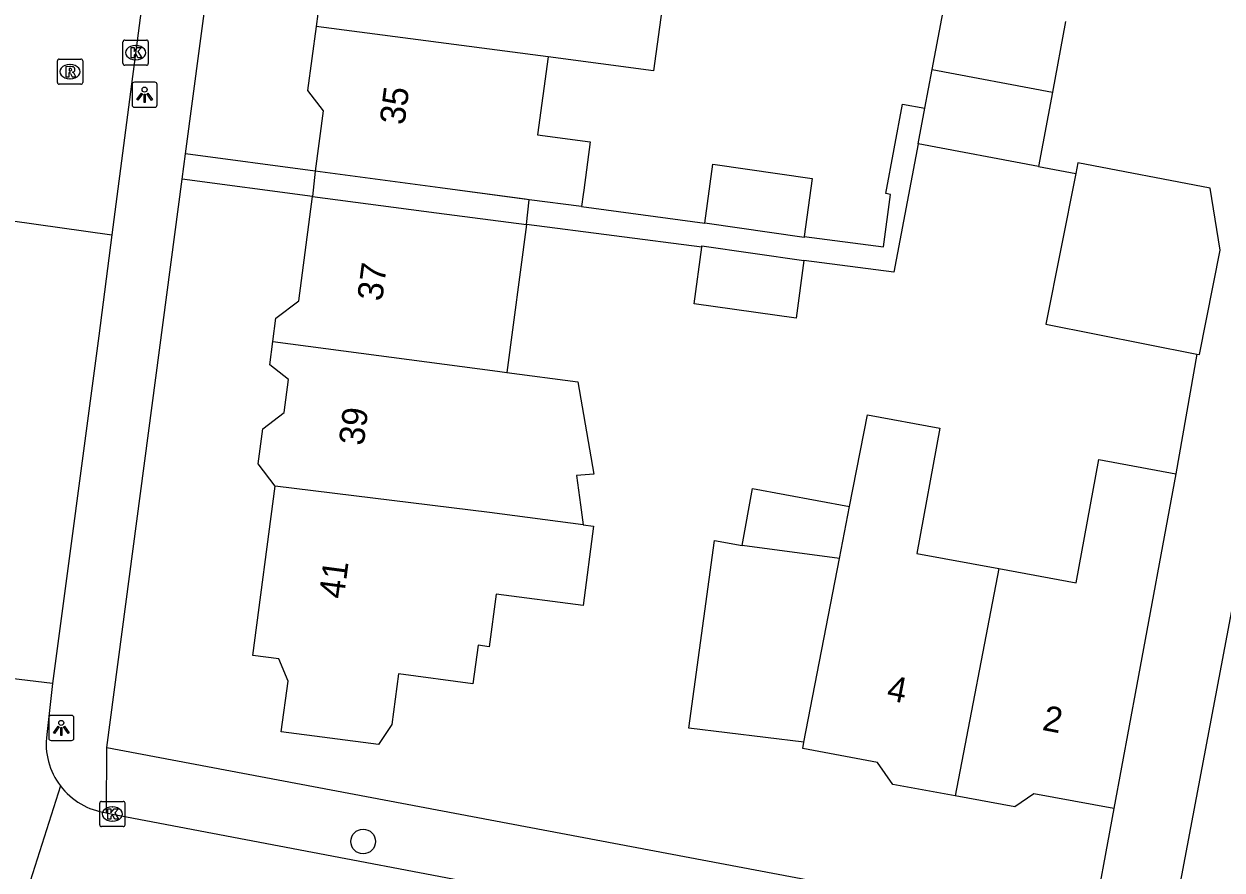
# Model space of a CAD drawing. Extents: x 161258 to 161838, y 380836 to 381727.
# Drawn here: x 161739.61 to 161787.11, y 381543.22 to 381576.79 of the extents above; entities that cross this region are included whole.
import ezdxf

# ---------------------------------------------------------------- set-up
doc = ezdxf.new("R2010")
doc.units = 0
for name, color, linetype in [('IMGEO_Boom', 7, 'Continuous'), ('IMGEO_Kolk', 7, 'Continuous'), ('IMGEO_Lichtpunt', 7, 'Continuous'), ('IMGEO_Pand', 7, 'Continuous'), ('IMGEO_Pand_nummerreeks', 7, 'Continuous'), ('IMGEO_Pand_overbouw', 7, 'Continuous'), ('IMGEO_Rijbaan_lokaal_open', 7, 'Continuous'), ('IMGEO_Rioolput', 7, 'Continuous'), ('IMGEO_Voetpad_open', 7, 'Continuous')]:
    doc.layers.add(name, color=color, linetype=linetype)

msp = doc.modelspace()

# ---------------------------------------------------------------- linework, layer by layer
at = {"layer": 'IMGEO_Boom'}
msp.add_circle((161753.055, 381544.356), 0.489, dxfattribs=at)
at = {"layer": 'IMGEO_Kolk'}
for p, q in [((161743.533, 381575.221), (161743.533, 381576.073)), ((161743.608, 381576.147), (161744.46, 381576.147)), ((161744.021, 381575.927), (161744.046, 381575.927)), ((161744.534, 381576.073), (161744.534, 381575.221)), ((161744.044, 381575.367), (161744.019, 381575.367)), ((161744.46, 381575.147), (161743.608, 381575.147)), ((161742.686, 381545.945), (161743.538, 381545.945)), ((161742.611, 381545.019), (161742.611, 381545.871)), ((161743.099, 381545.725), (161743.124, 381545.725)), ((161743.612, 381545.871), (161743.612, 381545.019)), ((161743.538, 381544.945), (161742.686, 381544.945)), ((161743.122, 381545.165), (161743.097, 381545.165))]:
    msp.add_line(p, q, dxfattribs=at)
for points in [[(161743.533, 381575.221), (161743.533, 381576.073)], [(161743.608, 381576.147), (161744.46, 381576.147)], [(161743.854, 381575.847), (161743.977, 381575.847), (161743.977, 381575.696), (161744.107, 381575.847), (161744.271, 381575.847), (161744.125, 381575.696), (161744.278, 381575.447), (161744.126, 381575.447), (161744.041, 381575.611), (161743.977, 381575.544), (161743.977, 381575.447), (161743.854, 381575.447), (161743.854, 381575.847)], [(161744.534, 381576.073), (161744.534, 381575.221)], [(161744.46, 381575.147), (161743.608, 381575.147)], [(161742.686, 381545.945), (161743.538, 381545.945)], [(161742.611, 381545.019), (161742.611, 381545.871)], [(161742.932, 381545.645), (161743.055, 381545.645), (161743.055, 381545.494), (161743.185, 381545.645), (161743.349, 381545.645), (161743.203, 381545.494), (161743.356, 381545.245), (161743.204, 381545.245), (161743.119, 381545.409), (161743.055, 381545.342), (161743.055, 381545.245), (161742.932, 381545.245), (161742.932, 381545.645)], [(161743.612, 381545.871), (161743.612, 381545.019)], [(161743.538, 381544.945), (161742.686, 381544.945)]]:
    msp.add_lwpolyline(points, dxfattribs=at)
for centre, start, end in [((161743.61, 381576.071), 91.552, 178.448), ((161743.61, 381576.071), 91.552, 178.448), ((161744.458, 381576.071), 1.552, 88.448), ((161744.458, 381576.071), 1.552, 88.448), ((161743.61, 381575.223), 181.552, 268.448), ((161743.61, 381575.223), 181.552, 268.448), ((161744.458, 381575.223), 271.552, 358.448), ((161744.458, 381575.223), 271.552, 358.448), ((161742.688, 381545.869), 91.552, 178.448), ((161742.688, 381545.869), 91.552, 178.448), ((161743.536, 381545.869), 1.552, 88.448), ((161743.536, 381545.869), 1.552, 88.448), ((161742.688, 381545.021), 181.552, 268.448), ((161742.688, 381545.021), 181.552, 268.448), ((161743.536, 381545.021), 271.552, 358.448), ((161743.536, 381545.021), 271.552, 358.448)]:
    msp.add_arc(centre, 0.0765, start, end, dxfattribs=at)
for centre, major_axis, ratio, start_param, end_param in [((161744.02, 381575.647), (-0.387, 0.002), 0.722429, 4.712389, 7.853982), ((161744.045, 381575.647), (-0.39, 0.002), 0.717154, 1.570796, 4.712389), ((161743.098, 381545.445), (-0.387, 0.002), 0.722429, 4.712389, 7.853982), ((161743.123, 381545.445), (-0.39, 0.002), 0.717154, 1.570796, 4.712389)]:
    msp.add_ellipse(centre, major_axis=major_axis, ratio=ratio, start_param=start_param, end_param=end_param, dxfattribs=at)
at = {"layer": 'IMGEO_Lichtpunt'}
for p, q in [((161744.793, 381574.478), (161743.985, 381574.478)), ((161744.793, 381574.478), (161743.985, 381574.478)), ((161743.891, 381574.383), (161743.891, 381573.576)), ((161743.891, 381574.383), (161743.891, 381573.576)), ((161744.887, 381573.576), (161744.887, 381574.383)), ((161744.887, 381573.576), (161744.887, 381574.383)), ((161743.985, 381573.482), (161744.793, 381573.482)), ((161743.985, 381573.482), (161744.793, 381573.482)), ((161740.588, 381549.263), (161740.588, 381548.456)), ((161740.588, 381549.263), (161740.588, 381548.456)), ((161741.49, 381549.358), (161740.682, 381549.358)), ((161741.49, 381549.358), (161740.682, 381549.358)), ((161741.584, 381548.456), (161741.584, 381549.263)), ((161741.584, 381548.456), (161741.584, 381549.263)), ((161740.682, 381548.362), (161741.49, 381548.362)), ((161740.682, 381548.362), (161741.49, 381548.362))]:
    msp.add_line(p, q, dxfattribs=at)
for points in [[(161744.265, 381574.047), (161744.304, 381574.019), (161744.116, 381573.757), (161744.078, 381573.784), (161744.265, 381574.047)], [(161744.367, 381573.999), (161744.414, 381573.999), (161744.414, 381573.677), (161744.367, 381573.677), (161744.367, 381573.999)], [(161744.477, 381574.019), (161744.515, 381574.046), (161744.702, 381573.784), (161744.663, 381573.756), (161744.477, 381574.019)], [(161740.962, 381548.927), (161741.001, 381548.899), (161740.813, 381548.637), (161740.775, 381548.664), (161740.962, 381548.927)], [(161741.064, 381548.879), (161741.111, 381548.879), (161741.111, 381548.557), (161741.064, 381548.557), (161741.064, 381548.879)], [(161741.174, 381548.899), (161741.212, 381548.926), (161741.399, 381548.664), (161741.36, 381548.636), (161741.174, 381548.899)]]:
    msp.add_lwpolyline(points, dxfattribs=at)
for centre in [(161744.39, 381574.181), (161741.087, 381549.061)]:
    msp.add_circle(centre, 0.0994, dxfattribs=at)
for centre, start, end in [((161743.985, 381574.383), 90, 180), ((161743.985, 381574.383), 90, 180), ((161744.793, 381574.383), 0, 90), ((161744.793, 381574.383), 0, 90), ((161743.985, 381573.576), 180, 270), ((161743.985, 381573.576), 180, 270), ((161744.793, 381573.576), 270, 0), ((161744.793, 381573.576), 270, 360), ((161740.682, 381549.263), 90, 180), ((161740.682, 381549.263), 90, 180), ((161741.49, 381549.263), 0, 90), ((161741.49, 381549.263), 0, 90), ((161740.682, 381548.456), 180, 270), ((161740.682, 381548.456), 180, 270), ((161741.49, 381548.456), 270, 0), ((161741.49, 381548.456), 270, 360)]:
    msp.add_arc(centre, 0.0946, start, end, dxfattribs=at)
at = {"layer": 'IMGEO_Pand'}
for points in [[(161752.637, 381582.578), (161752.295, 381580.008), (161751.591, 381579.718), (161751.188, 381576.688)], [(161765.382, 381580.905), (161764.569, 381574.925), (161760.386, 381575.481)], [(161775.614, 381574.978), (161776.143, 381577.779)], [(161780.909, 381576.885), (161780.383, 381574.083)], [(161751.188, 381576.688), (161750.85, 381574.15), (161751.47, 381573.34), (161751.151, 381570.945)], [(161760.386, 381575.481), (161751.188, 381576.688)], [(161760.386, 381575.481), (161759.974, 381572.383), (161762.057, 381572.106), (161761.802, 381570.188), (161761.78, 381570.023), (161761.716, 381569.539)], [(161775.323, 381573.443), (161775.614, 381574.978)], [(161775.614, 381574.978), (161780.383, 381574.083)], [(161780.383, 381574.083), (161779.83, 381571.134)], [(161775.056, 381572.03), (161775.323, 381573.443)], [(161779.83, 381571.134), (161775.056, 381572.03)], [(161766.606, 381568.883), (161766.925, 381571.218), (161770.856, 381570.657), (161770.543, 381568.361)], [(161786.11, 381563.693), (161786.221, 381563.671), (161787.039, 381567.813), (161786.642, 381570.271), (161781.392, 381571.272), (161781.308, 381570.848)], [(161761.716, 381569.539), (161759.633, 381569.816), (161759.477, 381569.837), (161756.106, 381570.285), (161751.151, 381570.945)], [(161781.308, 381570.848), (161780.129, 381564.875), (161786.11, 381563.693)], [(161749.473, 381564.184), (161749.596, 381565.112), (161750.502, 381565.805), (161751.052, 381569.945)], [(161751.052, 381569.945), (161755.97, 381569.291), (161759.538, 381568.828)], [(161759.538, 381568.828), (161758.757, 381562.958)], [(161770.543, 381568.361), (161770.537, 381568.321), (161766.606, 381568.883)], [(161770.531, 381567.408), (161770.218, 381565.109), (161766.176, 381565.687), (161766.483, 381567.931)], [(161766.483, 381567.931), (161766.49, 381567.985), (161770.531, 381567.408)], [(161749.571, 381558.447), (161748.888, 381559.339), (161749.073, 381560.729), (161749.92, 381561.377), (161750.094, 381562.687), (161749.35, 381563.26), (161749.473, 381564.184)], [(161749.473, 381564.184), (161758.385, 381563.007), (161758.757, 381562.958)], [(161758.757, 381562.958), (161761.564, 381562.587), (161762.203, 381558.933), (161761.521, 381558.873), (161761.674, 381557.714), (161761.78, 381556.919)], [(161772.338, 381557.644), (161773.051, 381561.278), (161775.927, 381560.746), (161775.01, 381555.779), (161778.26, 381555.179)], [(161778.26, 381555.179), (161781.325, 381554.613), (161782.228, 381559.503), (161785.277, 381558.94)], [(161785.277, 381558.94), (161783.734, 381550.581), (161782.826, 381545.664)], [(161761.78, 381556.919), (161762.195, 381556.864), (161761.776, 381553.714), (161758.327, 381554.173), (161758.048, 381552.081), (161757.612, 381552.139), (161757.409, 381550.612), (161754.455, 381551.005), (161754.187, 381548.993), (161753.667, 381548.199), (161749.811, 381548.712), (161750.077, 381550.714), (161749.711, 381551.601), (161748.679, 381551.738), (161749.571, 381558.447)], [(161761.78, 381556.919), (161758.068, 381557.413), (161749.571, 381558.447)], [(161768.079, 381556.099), (161768.496, 381558.354), (161772.338, 381557.644)], [(161771.941, 381555.585), (161772.338, 381557.644)], [(161770.533, 381548.301), (161765.971, 381548.847), (161766.984, 381556.295), (161768.079, 381556.099)], [(161771.941, 381555.585), (161768.079, 381556.099)], [(161770.533, 381548.301), (161771.941, 381555.585)], [(161778.26, 381555.179), (161776.522, 381546.166)], [(161776.522, 381546.166), (161774.055, 381546.621), (161773.453, 381547.496), (161770.485, 381548.044), (161770.533, 381548.301)], [(161782.826, 381545.664), (161779.651, 381546.251), (161778.892, 381545.728), (161776.522, 381546.166)]]:
    msp.add_lwpolyline(points, dxfattribs=at)
at = {"layer": 'IMGEO_Pand_overbouw'}
msp.add_lwpolyline([(161751.052, 381569.945), (161755.97, 381569.291), (161759.538, 381568.828), (161759.633, 381569.816), (161756.106, 381570.285), (161751.151, 381570.945)], close=True, dxfattribs=at)
at = {"layer": 'IMGEO_Rijbaan_lokaal_open'}
for points in [[(161784.977, 381540.142), (161793.109, 381583.267), (161782.505, 381585.389)], [(161744.761, 381581.189), (161743.094, 381568.418)], [(161779.83, 381571.134), (161781.308, 381570.848)], [(161739.062, 381568.989), (161743.094, 381568.418)], [(161743.094, 381568.418), (161742.572, 381564.421), (161740.738, 381550.621)], [(161786.11, 381563.693), (161785.277, 381558.94)], [(161740.738, 381550.621), (161736.87, 381551.083)], [(161740.738, 381550.621), (161740.508, 381548.595)], [(161741.055, 381546.559), (161739.018, 381540.168)], [(161742.875, 381545.494), (161743.113, 381545.444), (161764.536, 381541.372), (161764.753, 381541.307), (161769.655, 381540.387), (161774.599, 381539.471), (161775.772, 381539.26)], [(161782.826, 381545.664), (161781.913, 381540.72)]]:
    msp.add_lwpolyline(points, dxfattribs=at)
for centre, radius, start, end in [((161743.265, 381548.244), 2.779, 172.7505, 217.326), ((161743.262, 381548.244), 2.777, 217.3503, 261.9804)]:
    msp.add_arc(centre, radius, start, end, dxfattribs=at)
at = {"layer": 'IMGEO_Rioolput'}
for p, q in [((161741.008, 381575.394), (161741.86, 381575.394)), ((161740.933, 381574.468), (161740.933, 381575.32)), ((161741.421, 381575.174), (161741.446, 381575.174)), ((161741.934, 381575.32), (161741.934, 381574.468)), ((161741.86, 381574.394), (161741.008, 381574.394)), ((161741.444, 381574.614), (161741.419, 381574.614))]:
    msp.add_line(p, q, dxfattribs=at)
for points in [[(161741.008, 381575.394), (161741.86, 381575.394)], [(161740.933, 381574.468), (161740.933, 381575.32)], [(161741.522, 381575.092), (161741.27, 381575.094), (161741.27, 381574.694)], [(161741.448, 381575.013), (161741.394, 381575.013), (161741.394, 381574.932)], [(161741.394, 381574.932), (161741.446, 381574.932)], [(161741.934, 381575.32), (161741.934, 381574.468)], [(161741.86, 381574.394), (161741.008, 381574.394)], [(161741.27, 381574.694), (161741.394, 381574.694), (161741.394, 381574.856), (161741.405, 381574.856)], [(161741.452, 381574.827), (161741.523, 381574.694), (161741.663, 381574.694), (161741.598, 381574.82)]]:
    msp.add_lwpolyline(points, dxfattribs=at)
for centre, radius, start, end in [((161741.01, 381575.318), 0.0765, 91.552, 178.448), ((161741.01, 381575.318), 0.0765, 91.552, 178.448), ((161741.858, 381575.318), 0.0765, 1.552, 88.448), ((161741.858, 381575.318), 0.0765, 1.552, 88.448), ((161741.43, 381575.121), 0.19, 274.7715, 282.9687), ((161741.454, 381574.917), 0.0964, 77.0061, 93.1865), ((161741.468, 381574.974), 0.0378, 276.6634, 79.6772), ((161741.521, 381574.982), 0.109, 350.3612, 89.416), ((161741.519, 381574.982), 0.112, 277.5842, 350.9817), ((161741.503, 381574.767), 0.108, 29.5134, 73.7905), ((161741.01, 381574.47), 0.0765, 181.552, 268.448), ((161741.01, 381574.47), 0.0765, 181.552, 268.448), ((161741.404, 381574.803), 0.0533, 26.0293, 88.6989), ((161741.858, 381574.47), 0.0765, 271.552, 358.448), ((161741.858, 381574.47), 0.0765, 271.552, 358.448)]:
    msp.add_arc(centre, radius, start, end, dxfattribs=at)
for centre, major_axis, ratio, start_param, end_param in [((161741.42, 381574.894), (-0.387, 0.002), 0.722429, 4.712389, 7.853982), ((161741.445, 381574.894), (-0.39, 0.002), 0.717154, 1.570796, 4.712389)]:
    msp.add_ellipse(centre, major_axis=major_axis, ratio=ratio, start_param=start_param, end_param=end_param, dxfattribs=at)
at = {"layer": 'IMGEO_Voetpad_open'}
for points in [[(161746.014, 381571.629), (161749.249, 381596.016)], [(161770.543, 381568.361), (161773.688, 381567.947), (161773.964, 381570.026), (161773.775, 381570.062), (161774.446, 381573.609), (161775.323, 381573.443)], [(161775.056, 381572.03), (161774.092, 381566.939), (161770.531, 381567.408)], [(161745.882, 381570.631), (161746.014, 381571.629)], [(161751.151, 381570.945), (161746.014, 381571.629)], [(161742.891, 381548.079), (161745.882, 381570.631)], [(161751.052, 381569.945), (161745.882, 381570.631)], [(161761.716, 381569.539), (161766.606, 381568.883)], [(161766.483, 381567.931), (161759.538, 381568.828)], [(161742.875, 381545.494), (161742.891, 381548.079)], [(161742.891, 381548.079), (161781.913, 381540.72)]]:
    msp.add_lwpolyline(points, dxfattribs=at)

# ---------------------------------------------------------------- texts
at = {"layer": 'IMGEO_Pand_nummerreeks'}
for s, rotation, p in [('35', 82.5919, (161754.693, 381572.753)), ('37', 82.4314, (161753.805, 381565.761)), ('39', 82.8382, (161753.076, 381560.033)), ('41', 82.4257, (161752.283, 381553.953)), ('4', 349.0843, (161773.777, 381549.976)), ('2', 349.0843, (161779.946, 381548.787))]:
    msp.add_text(s, height=1, rotation=rotation, dxfattribs=at).set_placement(p)

doc.saveas('drawing.dxf')
